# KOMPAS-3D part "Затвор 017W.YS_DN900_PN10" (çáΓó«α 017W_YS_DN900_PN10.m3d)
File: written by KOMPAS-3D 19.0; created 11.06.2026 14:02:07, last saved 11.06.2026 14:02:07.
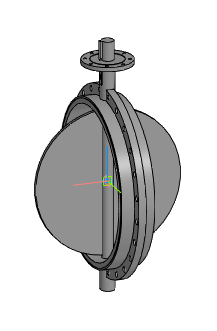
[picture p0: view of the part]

Document properties: Автор: Евгений; Полное имя файла: Z:\3.Личные\kachalov\001_3d для проектировщиков\x.x Тип 017W.Y(S) Затвор дисковый поворотный межфланцевый\_stp_Затвор 017W.YS_DN32-DN1200\Затвор 017W_YS_DN900_PN10.m3d

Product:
- Part/product: Затвор 017W.YS_DN900_PN10

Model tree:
1. Операция без истории:1  (labels: Затвор 017W.YS_DN900_PN10)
